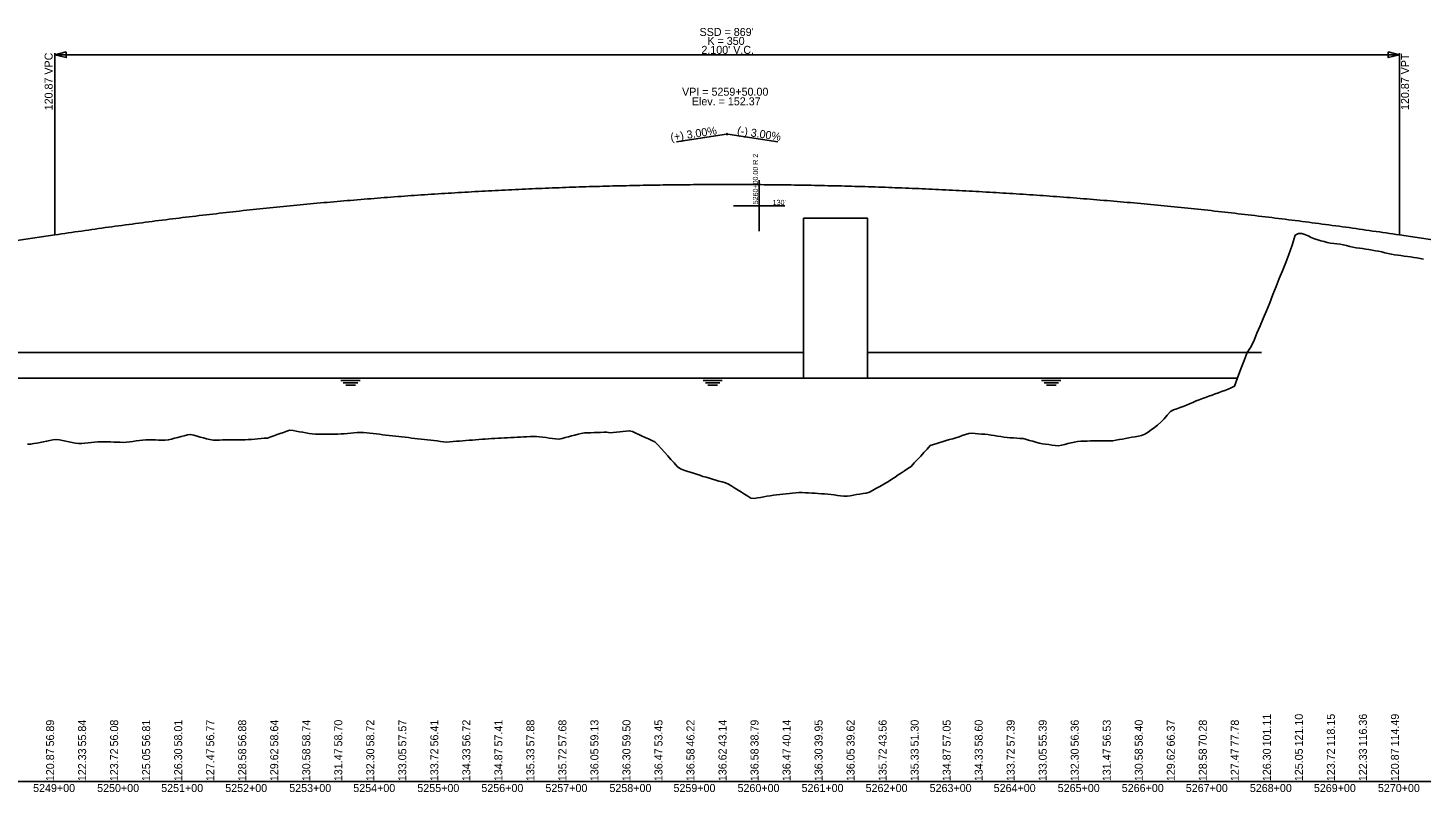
# Model space of a CAD drawing. Extents: x 2147288 to 2220488, y 740833 to 759333.
# Drawn here: x 2157239 to 2159415, y 750067 to 751261 of the extents above; entities that cross this region are included whole.
import ezdxf

# ---------------------------------------------------------------- set-up
doc = ezdxf.new("R2010")
doc.units = 0
for name, color, linetype in [('RD_DDB_GradeTX', 7, 'Continuous'), ('RD_DDB_Profile_Elev', 7, 'Continuous'), ('RD_DDB_Profile_EX', 7, 'Continuous'), ('RD_DDB_Profile_Lbl', 7, 'Continuous'), ('RD_DDB_Profile_PR', 7, 'Continuous'), ('RD_DDB_StaTX', 7, 'Continuous'), ('RD_DDB_StripGrade', 7, 'Continuous'), ('RD_DDB_VCLbl', 7, 'Continuous'), ('RD_GPK_Profile_Cell', 7, 'Continuous')]:
    doc.layers.add(name, color=color, linetype=linetype)

msp = doc.modelspace()

# ---------------------------------------------------------------- linework, layer by layer
at = {"layer": 'RD_DDB_GradeTX'}
for p, q in [((2158252, 751083.4), (2158330.1, 751095.1)), ((2158410.2, 751083.4), (2158332.1, 751095.1))]:
    msp.add_line(p, q, dxfattribs=at)
msp.add_circle((2158331.1, 751095.3), 1, dxfattribs=at)
at = {"layer": 'RD_DDB_Profile_Elev'}
for p, q in [((2154716.7, 750754), (2158451.2, 750754)), ((2158551.2, 750754), (2159165.5, 750754)), ((2154763.1, 750714), (2159128.1, 750714)), ((2157728, 750710.3), (2157758, 750710.3)), ((2157731.7, 750706.5), (2157754.2, 750706.5)), ((2157735.5, 750702.8), (2157750.5, 750702.8)), ((2158293.5, 750710.3), (2158323.5, 750710.3)), ((2158297.2, 750706.5), (2158319.7, 750706.5)), ((2158301, 750702.8), (2158316, 750702.8)), ((2158822.2, 750710.3), (2158852.2, 750710.3)), ((2158825.9, 750706.5), (2158848.4, 750706.5)), ((2158829.7, 750702.8), (2158844.7, 750702.8))]:
    msp.add_line(p, q, dxfattribs=at)
msp.add_lwpolyline([(2158450.2, 750964), (2158550.2, 750964), (2158550.2, 750714), (2158450.2, 750714)], close=True, dxfattribs=at)
at = {"layer": 'RD_DDB_Profile_EX'}
for points in [[(2159038.3, 750668), (2159043.3, 750669.8), (2159048.3, 750671.8), (2159053.3, 750674), (2159058.3, 750676.1), (2159063.3, 750678.3), (2159068.3, 750680.1), (2159073.3, 750682), (2159078.3, 750683.8), (2159083.3, 750685.6), (2159088.3, 750687.5), (2159093.3, 750689.3), (2159098.3, 750691.2), (2159103.3, 750693), (2159108.3, 750694.9), (2159113.3, 750696.7), (2159118.3, 750698.6), (2159123.3, 750701.4), (2159128.3, 750714.6), (2159133.3, 750728.4), (2159138.3, 750741.8), (2159143.3, 750753.9), (2159148.3, 750761.7), (2159153.3, 750771.8), (2159158.3, 750784.5), (2159163.3, 750795.7), (2159168.3, 750807), (2159173.3, 750819.3), (2159178.3, 750831.6), (2159183.3, 750844.8), (2159188.3, 750857.2), (2159193.3, 750869.9), (2159198.3, 750881.8), (2159203.3, 750894.7), (2159208.3, 750907.2), (2159213.3, 750921.8), (2159218.3, 750937.4), (2159223.3, 750940.2), (2159228.3, 750939.8), (2159233.3, 750938.2), (2159238.3, 750936.5), (2159243.3, 750934), (2159248.3, 750931.7), (2159253.3, 750930), (2159258.3, 750928.7), (2159263.3, 750927.4), (2159268.3, 750925.8), (2159273.3, 750925), (2159278.3, 750924.5), (2159283.3, 750923.9), (2159288.3, 750923.2), (2159293.3, 750922.3), (2159298.3, 750921.2), (2159303.3, 750919.7), (2159308.3, 750918.4), (2159313.3, 750917.7), (2159318.3, 750917.1), (2159323.3, 750916.4), (2159328.3, 750915.6), (2159333.3, 750914.9), (2159338.3, 750914.2), (2159343.3, 750913.1), (2159348.3, 750912.2), (2159353.3, 750911.1), (2159358.3, 750909.9), (2159363.3, 750908.8), (2159368.3, 750907.6), (2159373.3, 750906.8), (2159378.3, 750906.2), (2159383.3, 750905.6), (2159388.3, 750904.8), (2159393.3, 750904.1), (2159398.3, 750903.5), (2159403.3, 750902.7), (2159408.3, 750901.8), (2159413.3, 750900.9), (2159418.3, 750900)], [(2158538.3, 750532.7), (2158543.3, 750533.5), (2158548.3, 750534.3), (2158553.3, 750535.7), (2158558.3, 750538.5), (2158563.3, 750541.3), (2158568.3, 750544.1), (2158573.3, 750546.9), (2158578.3, 750549.7), (2158583.3, 750552.5), (2158588.3, 750556.1), (2158593.3, 750559.4), (2158598.3, 750562.7), (2158603.3, 750566), (2158608.3, 750569.3), (2158613.3, 750572.7), (2158618.3, 750576), (2158623.3, 750581.4), (2158628.3, 750586.9), (2158633.3, 750592.3), (2158638.3, 750597.8), (2158643.3, 750603.2), (2158648.3, 750608.7), (2158653.3, 750610.5), (2158658.3, 750612), (2158663.3, 750613.5), (2158668.3, 750615), (2158673.3, 750616.5), (2158678.3, 750618.1), (2158683.3, 750619.2), (2158688.3, 750620.9), (2158693.3, 750622.5), (2158698.3, 750624.2), (2158703.3, 750625.9), (2158708.3, 750627.6), (2158713.3, 750627.8), (2158718.3, 750627.4), (2158723.3, 750627), (2158728.3, 750626.6), (2158733.3, 750626.3), (2158738.3, 750625.9), (2158743.3, 750625.1), (2158748.3, 750624.2), (2158753.3, 750623.4), (2158758.3, 750622.6), (2158763.3, 750621.8), (2158768.3, 750621.2), (2158773.3, 750620.9), (2158778.3, 750620.5), (2158783.3, 750620.2), (2158788.3, 750619.9), (2158793.3, 750619.5), (2158798.3, 750618.2), (2158803.3, 750616.7), (2158808.3, 750615.3), (2158813.3, 750613.9), (2158818.3, 750612.5), (2158823.3, 750611.4), (2158828.3, 750610.7), (2158833.3, 750610.1), (2158838.3, 750609.4), (2158843.3, 750608.8), (2158848.3, 750608.1), (2158853.3, 750609), (2158858.3, 750610.3), (2158863.3, 750611.6), (2158868.3, 750612.9), (2158873.3, 750614.1), (2158878.3, 750615.1), (2158883.3, 750615.3), (2158888.3, 750615.5), (2158893.3, 750615.7), (2158898.3, 750615.9), (2158903.3, 750616), (2158908.3, 750616), (2158913.3, 750616), (2158918.3, 750616), (2158923.3, 750616), (2158928.3, 750616), (2158933.3, 750616.2), (2158938.3, 750617.1), (2158943.3, 750617.9), (2158948.3, 750618.8), (2158953.3, 750619.7), (2158958.3, 750620.5), (2158963.3, 750621.5), (2158968.3, 750622.4), (2158973.3, 750623.3), (2158978.3, 750624.3), (2158983.3, 750626.3), (2158988.3, 750629.8), (2158993.3, 750633.3), (2158998.3, 750636.8), (2159003.3, 750640.3), (2159008.3, 750645), (2159013.3, 750650.6), (2159018.3, 750656.2), (2159023.3, 750661.8), (2159028.3, 750664.3), (2159033.3, 750666.1), (2159038.3, 750668)], [(2157538.3, 750617.3), (2157543.3, 750617.4), (2157548.3, 750617.4), (2157553.3, 750617.5), (2157558.3, 750617.5), (2157563.3, 750617.4), (2157568.3, 750617.4), (2157573.3, 750617.5), (2157578.3, 750617.7), (2157583.3, 750617.9), (2157588.3, 750618.2), (2157593.3, 750618.7), (2157598.3, 750619.1), (2157603.3, 750619.6), (2157608.3, 750620.1), (2157613.3, 750620.4), (2157618.3, 750622.2), (2157623.3, 750623.9), (2157628.3, 750625.7), (2157633.3, 750627.4), (2157638.3, 750629.2), (2157643.3, 750630.9), (2157648.3, 750632.6), (2157653.3, 750631.9), (2157658.3, 750631.1), (2157663.3, 750630.2), (2157668.3, 750629.3), (2157673.3, 750628.5), (2157678.3, 750627.6), (2157683.3, 750626.7), (2157688.3, 750626.4), (2157693.3, 750626.4), (2157698.3, 750626.4), (2157703.3, 750626.4), (2157708.3, 750626.4), (2157713.3, 750626.4), (2157718.3, 750626.4), (2157723.3, 750626.3), (2157728.3, 750626.7), (2157733.3, 750627.1), (2157738.3, 750627.5), (2157743.3, 750627.9), (2157748.3, 750628.4), (2157753.3, 750628.8), (2157758.3, 750629.2), (2157763.3, 750629.1), (2157768.3, 750628.5), (2157773.3, 750627.9), (2157778.3, 750627.4), (2157783.3, 750626.8), (2157788.3, 750626.2), (2157793.3, 750625.6), (2157798.3, 750625), (2157803.3, 750624.5), (2157808.3, 750623.9), (2157813.3, 750623.3), (2157818.3, 750622.7), (2157823.3, 750622.2), (2157828.3, 750621.6), (2157833.3, 750621), (2157838.3, 750620.4), (2157843.3, 750619.8), (2157848.3, 750619.3), (2157853.3, 750618.7), (2157858.3, 750618.1), (2157863.3, 750617.5), (2157868.3, 750617), (2157873.3, 750616.4), (2157878.3, 750615.8), (2157883.3, 750615.2), (2157888.3, 750614.6), (2157893.3, 750614.1), (2157898.3, 750614.5), (2157903.3, 750614.9), (2157908.3, 750615.3), (2157913.3, 750615.6), (2157918.3, 750616), (2157923.3, 750616.4), (2157928.3, 750616.8), (2157933.3, 750617.2), (2157938.3, 750617.6), (2157943.3, 750618), (2157948.3, 750618.4), (2157953.3, 750618.8), (2157958.3, 750619.1), (2157963.3, 750619.4), (2157968.3, 750619.7), (2157973.3, 750620), (2157978.3, 750620.3), (2157983.3, 750620.6), (2157988.3, 750620.9), (2157993.3, 750621.2), (2157998.3, 750621.4), (2158003.3, 750621.6), (2158008.3, 750621.9), (2158013.3, 750622.1), (2158018.3, 750622.4), (2158023.3, 750622.6), (2158028.3, 750622.9), (2158033.3, 750622.8), (2158038.3, 750622.2)], [(2158038.3, 750622.2), (2158043.3, 750621.6), (2158048.3, 750621), (2158053.3, 750620.3), (2158058.3, 750619.7), (2158063.3, 750619.1), (2158068.3, 750618.5), (2158073.3, 750619.8), (2158078.3, 750621.1), (2158083.3, 750622.4), (2158088.3, 750623.7), (2158093.3, 750625), (2158098.3, 750626.3), (2158103.3, 750627.6), (2158108.3, 750628.3), (2158113.3, 750628.4), (2158118.3, 750628.6), (2158123.3, 750628.8), (2158128.3, 750629), (2158133.3, 750629.1), (2158138.3, 750629.3), (2158143.3, 750629.5), (2158148.3, 750628.7), (2158153.3, 750629.2), (2158158.3, 750629.7), (2158163.3, 750630.2), (2158168.3, 750630.7), (2158173.3, 750631.2), (2158178.3, 750631.7), (2158183.3, 750630.4), (2158188.3, 750628.1), (2158193.3, 750625.8), (2158198.3, 750623.5), (2158203.3, 750621.3), (2158208.3, 750619), (2158213.3, 750616.7), (2158218.3, 750614.5), (2158223.3, 750609.4), (2158228.3, 750603.8), (2158233.3, 750598.2), (2158238.3, 750592.6), (2158243.3, 750587), (2158248.3, 750581.4), (2158253.3, 750575.8), (2158258.3, 750572), (2158263.3, 750570.4), (2158268.3, 750568.7), (2158273.3, 750567.1), (2158278.3, 750565.5), (2158283.3, 750563.8), (2158288.3, 750562.2), (2158293.3, 750560.5), (2158298.3, 750559.1), (2158303.3, 750557.6), (2158308.3, 750556.1), (2158313.3, 750554.6), (2158318.3, 750553.2), (2158323.3, 750551.7), (2158328.3, 750550.2), (2158333.3, 750548.3), (2158338.3, 750545.2), (2158343.3, 750542), (2158348.3, 750538.8), (2158353.3, 750535.7), (2158358.3, 750532.5), (2158363.3, 750529.4), (2158368.3, 750526.2), (2158373.3, 750526.1), (2158378.3, 750526.9), (2158383.3, 750527.7), (2158388.3, 750528.5), (2158393.3, 750529.4), (2158398.3, 750530.2), (2158403.3, 750531), (2158408.3, 750531.7), (2158413.3, 750532.2), (2158418.3, 750532.7), (2158423.3, 750533.3), (2158428.3, 750533.8), (2158433.3, 750534.4), (2158438.3, 750534.9), (2158443.3, 750535.4), (2158448.3, 750535.3), (2158453.3, 750535), (2158458.3, 750534.7), (2158463.3, 750534.3), (2158468.3, 750534), (2158473.3, 750533.7), (2158478.3, 750533.4), (2158483.3, 750533.1), (2158488.3, 750532.5), (2158493.3, 750531.9), (2158498.3, 750531.4), (2158503.3, 750530.8), (2158508.3, 750530.2), (2158513.3, 750529.6), (2158518.3, 750529.5), (2158523.3, 750530.3), (2158528.3, 750531.1), (2158533.3, 750531.9), (2158538.3, 750532.7)], [(2157238.3, 750610.7), (2157243.3, 750610.6), (2157248.3, 750611.6), (2157253.3, 750612.6), (2157258.3, 750613.5), (2157263.3, 750614.5), (2157268.3, 750615.4), (2157273.3, 750616.4), (2157278.3, 750617.4), (2157283.3, 750618.3), (2157288.3, 750617.5), (2157293.3, 750616.5), (2157298.3, 750615.6), (2157303.3, 750614.6), (2157308.3, 750613.6), (2157313.3, 750612.6), (2157318.3, 750611.6), (2157323.3, 750611.9), (2157328.3, 750612.4), (2157333.3, 750612.8), (2157338.3, 750613.3), (2157343.3, 750613.7), (2157348.3, 750614.2), (2157353.3, 750614.7), (2157358.3, 750614.6), (2157363.3, 750614.5), (2157368.3, 750614.3), (2157373.3, 750614.1), (2157378.3, 750613.9), (2157383.3, 750613.8), (2157388.3, 750613.6), (2157393.3, 750614.1), (2157398.3, 750614.6), (2157403.3, 750615.2), (2157408.3, 750615.8), (2157413.3, 750616.4), (2157418.3, 750616.9), (2157423.3, 750617.5), (2157428.3, 750617.5), (2157433.3, 750617.4), (2157438.3, 750617.4), (2157443.3, 750617.3), (2157448.3, 750617.3), (2157453.3, 750617.3), (2157458.3, 750617.5), (2157463.3, 750618.8), (2157468.3, 750620.1), (2157473.3, 750621.4), (2157478.3, 750622.7), (2157483.3, 750624), (2157488.3, 750625.3), (2157493.3, 750626), (2157498.3, 750624.7), (2157503.3, 750623.3), (2157508.3, 750621.9), (2157513.3, 750620.6), (2157518.3, 750619.2), (2157523.3, 750617.9), (2157528.3, 750617.3), (2157533.3, 750617.3), (2157538.3, 750617.3)]]:
    msp.add_lwpolyline(points, dxfattribs=at)
at = {"layer": 'RD_DDB_Profile_PR'}
for p, q in [((2156931.1, 750885.3), (2157281.1, 750937.8)), ((2159381.1, 750937.8), (2159706.1, 750889))]:
    msp.add_line(p, q, dxfattribs=at)
msp.add_spline([(2157281.1, 750937.8), (2157323.1, 750943.9), (2157365.1, 750949.9), (2157407.1, 750955.5), (2157449.1, 750960.9), (2157491.1, 750966.1), (2157533.1, 750971), (2157575.1, 750975.7), (2157617.1, 750980.1), (2157659.1, 750984.3), (2157701.1, 750988.2), (2157743.1, 750991.8), (2157785.1, 750995.2), (2157827.1, 750998.4), (2157869.1, 751001.3), (2157911.1, 751003.9), (2157953.1, 751006.3), (2157995.1, 751008.4), (2158037.1, 751010.3), (2158079.1, 751012), (2158121.1, 751013.4), (2158163.1, 751014.5), (2158205.1, 751015.4), (2158247.1, 751016), (2158289.1, 751016.4), (2158331.1, 751016.5), (2158373.1, 751016.4), (2158415.1, 751016), (2158457.1, 751015.4), (2158499.1, 751014.5), (2158541.1, 751013.4), (2158583.1, 751012), (2158625.1, 751010.3), (2158667.1, 751008.4), (2158709.1, 751006.3), (2158751.1, 751003.9), (2158793.1, 751001.3), (2158835.1, 750998.4), (2158877.1, 750995.2), (2158919.1, 750991.8), (2158961.1, 750988.2), (2159003.1, 750984.3), (2159045.1, 750980.1), (2159087.1, 750975.7), (2159129.1, 750971), (2159171.1, 750966.1), (2159213.1, 750960.9), (2159255.1, 750955.5), (2159297.1, 750949.9), (2159339.1, 750943.9), (2159381.1, 750937.8)], degree=3, dxfattribs=at)
at = {"layer": 'RD_DDB_VCLbl'}
for p, q in [((2157281.1, 751221.9), (2157281.1, 750937.8)), ((2157281.1, 751219.4), (2159381.1, 751219.4)), ((2159381.1, 751221.9), (2159381.1, 750937.8))]:
    msp.add_line(p, q, dxfattribs=at)
for points in [[(2157299.1, 751223.9), (2157281.1, 751219.4), (2157299.1, 751214.9)], [(2159363.1, 751223.9), (2159381.1, 751219.4), (2159363.1, 751214.9)]]:
    msp.add_lwpolyline(points, close=True, dxfattribs=at)
at = {"layer": 'RD_GPK_Profile_Cell'}
for p, q in [((2158381.1, 751023.4), (2158381.1, 750943.4)), ((2158421.1, 750983.4), (2158341.1, 750983.4)), ((2148888.3, 750083.4), (2170488.3, 750083.4))]:
    msp.add_line(p, q, dxfattribs=at)

# ---------------------------------------------------------------- texts
at = {"layer": 'RD_DDB_GradeTX'}
for s, rotation, p in [('(+) 3.00%', 8.5308, (2158243.5, 751084.2)), ('(-) 3.00%', 351.4692, (2158346.1, 751095))]:
    msp.add_text(s, height=12.5, rotation=rotation, dxfattribs=at).set_placement(p)
at = {"layer": 'RD_DDB_Profile_Lbl'}
for s, p in [('VPI = 5259+50.00', (2158260.7, 751155.3)), ('Elev. = 152.37', (2158276, 751140.3))]:
    msp.add_text(s, height=12.5, dxfattribs=at).set_placement(p)
at = {"layer": 'RD_DDB_StaTX'}
for s, p in [('5249+00', (2157247.3, 750067.2)), ('5250+00', (2157347.3, 750067.2)), ('5251+00', (2157447.3, 750067.2)), ('5252+00', (2157547.3, 750067.2)), ('5253+00', (2157647.3, 750067.2)), ('5254+00', (2157747.3, 750067.2)), ('5255+00', (2157847.3, 750067.2)), ('5256+00', (2157947.3, 750067.2)), ('5257+00', (2158047.3, 750067.2)), ('5258+00', (2158147.3, 750067.2)), ('5259+00', (2158247.3, 750067.2)), ('5260+00', (2158347.3, 750067.2)), ('5261+00', (2158447.3, 750067.2)), ('5262+00', (2158547.3, 750067.2)), ('5263+00', (2158647.3, 750067.2)), ('5264+00', (2158747.3, 750067.2)), ('5265+00', (2158847.3, 750067.2)), ('5266+00', (2158947.3, 750067.2)), ('5267+00', (2159047.3, 750067.2)), ('5268+00', (2159147.3, 750067.2)), ('5269+00', (2159247.3, 750067.2)), ('5270+00', (2159347.3, 750067.2))]:
    msp.add_text(s, height=12.5, dxfattribs=at).set_placement(p)
at = {"layer": 'RD_DDB_StripGrade'}
for s, p in [('120.87 VPC', (2157277.8, 751132.5)), ('120.87 VPT', (2159395.9, 751133)), ('56.89', (2157280.1, 750138.4)), ('55.84', (2157330.1, 750138.4)), ('56.08', (2157380.1, 750138.4)), ('56.81', (2157430.1, 750138.4)), ('58.01', (2157480.1, 750138.4)), ('56.77', (2157530.1, 750138.4)), ('56.88', (2157580.1, 750138.4)), ('58.64', (2157630.1, 750138.4)), ('58.74', (2157680.1, 750138.4)), ('58.70', (2157730.1, 750138.4)), ('58.72', (2157780.1, 750138.4)), ('57.57', (2157830.1, 750138.4)), ('56.41', (2157880.1, 750138.4)), ('56.72', (2157930.1, 750138.4)), ('57.41', (2157980.1, 750138.4)), ('57.88', (2158030.1, 750138.4)), ('57.68', (2158080.1, 750138.4)), ('59.13', (2158130.1, 750138.4)), ('59.50', (2158180.1, 750138.4)), ('53.45', (2158230.1, 750138.4)), ('46.22', (2158280.1, 750138.4)), ('43.14', (2158330.1, 750138.4)), ('38.79', (2158380.1, 750138.4)), ('40.14', (2158430.1, 750138.4)), ('39.95', (2158480.1, 750138.4)), ('39.62', (2158530.1, 750138.4)), ('43.56', (2158580.1, 750138.4)), ('51.30', (2158630.1, 750138.4)), ('57.05', (2158680.1, 750138.4)), ('58.60', (2158730.1, 750138.4)), ('57.39', (2158780.1, 750138.4)), ('55.39', (2158830.1, 750138.4)), ('56.36', (2158880.1, 750138.4)), ('56.53', (2158930.1, 750138.4)), ('58.40', (2158980.1, 750138.4)), ('66.37', (2159030.1, 750138.4)), ('70.28', (2159080.1, 750138.4)), ('77.78', (2159130.1, 750138.4)), ('101.11', (2159180.1, 750138.4)), ('121.10', (2159230.1, 750138.4)), ('118.15', (2159280.1, 750138.4)), ('116.36', (2159330.1, 750138.4)), ('114.49', (2159380.1, 750138.4)), ('120.87', (2157280.1, 750084.2)), ('122.33', (2157330.1, 750084.2)), ('123.72', (2157380.1, 750084.2)), ('125.05', (2157430.1, 750084.2)), ('126.30', (2157480.1, 750084.2)), ('127.47', (2157530.1, 750084.2)), ('128.58', (2157580.1, 750084.2)), ('129.62', (2157630.1, 750084.2)), ('130.58', (2157680.1, 750084.2)), ('131.47', (2157730.1, 750084.2)), ('132.30', (2157780.1, 750084.2)), ('133.05', (2157830.1, 750084.2)), ('133.72', (2157880.1, 750084.2)), ('134.33', (2157930.1, 750084.2)), ('134.87', (2157980.1, 750084.2)), ('135.33', (2158030.1, 750084.2)), ('135.72', (2158080.1, 750084.2)), ('136.05', (2158130.1, 750084.2)), ('136.30', (2158180.1, 750084.2)), ('136.47', (2158230.1, 750084.2)), ('136.58', (2158280.1, 750084.2)), ('136.62', (2158330.1, 750084.2)), ('136.58', (2158380.1, 750084.2)), ('136.47', (2158430.1, 750084.2)), ('136.30', (2158480.1, 750084.2)), ('136.05', (2158530.1, 750084.2)), ('135.72', (2158580.1, 750084.2)), ('135.33', (2158630.1, 750084.2)), ('134.87', (2158680.1, 750084.2)), ('134.33', (2158730.1, 750084.2)), ('133.72', (2158780.1, 750084.2)), ('133.05', (2158830.1, 750084.2)), ('132.30', (2158880.1, 750084.2)), ('131.47', (2158930.1, 750084.2)), ('130.58', (2158980.1, 750084.2)), ('129.62', (2159030.1, 750084.2)), ('128.58', (2159080.1, 750084.2)), ('127.47', (2159130.1, 750084.2)), ('126.30', (2159180.1, 750084.2)), ('125.05', (2159230.1, 750084.2)), ('123.72', (2159280.1, 750084.2)), ('122.33', (2159330.1, 750084.2)), ('120.87', (2159380.1, 750084.2))]:
    msp.add_text(s, height=12.5, rotation=90, dxfattribs=at).set_placement(p)
at = {"layer": 'RD_DDB_VCLbl'}
for s, p in [("SSD = 869'", (2158288, 751248.7)), ('K = 350', (2158300.3, 751234.7)), ("2,100' V.C.", (2158290.9, 751220.7))]:
    msp.add_text(s, height=12.5, dxfattribs=at).set_placement(p)
at = {"layer": 'RD_GPK_Profile_Cell'}
msp.add_text('5260+00.00 R 2', height=8, rotation=90, dxfattribs=at).set_placement((2158379.3, 750985.7))
msp.add_text("130'", height=8, dxfattribs=at).set_placement((2158402.2, 750984.6))

doc.saveas('drawing.dxf')
